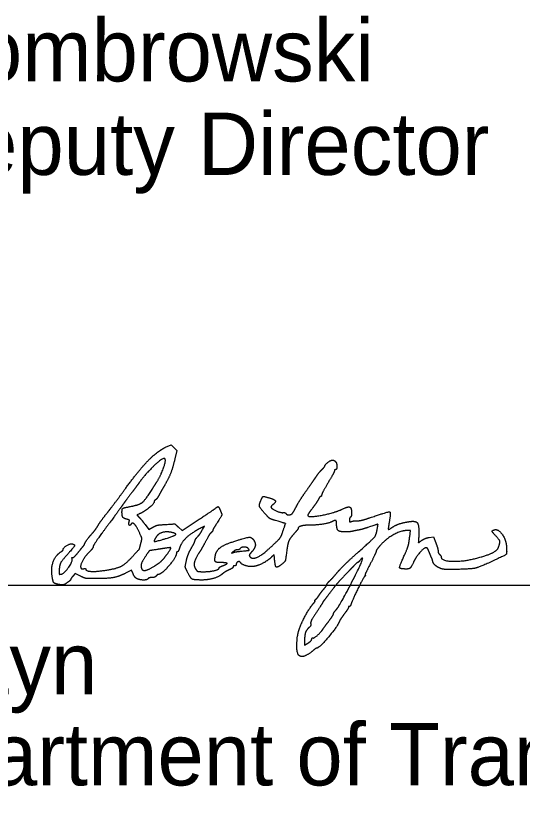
# Model space of a CAD drawing. Extents: x 0 to 42, y 0 to 22.
# Drawn here: x 25.7 to 26.838, y 7.063 to 8.834 of the extents above; entities that cross this region are included whole.
import ezdxf

# ---------------------------------------------------------------- set-up
doc = ezdxf.new("R2010")
doc.units = 0
for name, color, linetype in [('Default', 7, 'Continuous'), ('SH_Data', 7, 'Continuous'), ('SH_Text', 7, 'Continuous')]:
    doc.layers.add(name, color=color, linetype=linetype)

msp = doc.modelspace()

# ---------------------------------------------------------------- linework, layer by layer
at = {"layer": 'Default'}
for points in [[(26.0362, 7.8643), (26.0488, 7.8702), (26.0552, 7.8638), (26.0616, 7.8575), (26.0572, 7.8388)], [(25.9763, 7.7144), (25.9713, 7.7128), (25.9764, 7.7076)], [(25.9901, 7.691), (25.9987, 7.6794), (26.0075, 7.6847)], [(26.0653, 7.6847), (26.0734, 7.6771), (26.1096, 7.7012)], [(26.1191, 7.6794), (26.1236, 7.6873), (26.1181, 7.6844)], [(26.585, 7.6635), (26.5865, 7.6773), (26.5787, 7.6773)], [(26.6288, 7.6619), (26.6385, 7.6634), (26.6436, 7.6499)], [(26.2809, 7.6157), (26.2803, 7.6225), (26.2744, 7.6174)], [(25.8447, 7.5751), (25.8331, 7.5808), (25.8281, 7.575)], [(25.9633, 7.5801), (25.9599, 7.5881), (25.9461, 7.5813)], [(26.3487, 7.4296), (26.3487, 7.4202), (26.3562, 7.4245)]]:
    msp.add_lwpolyline(points, dxfattribs=at)
for points in [[(25.9467, 7.7725), (25.9763, 7.8131), (26.0181, 7.8559), (26.0362, 7.8643)], [(26.0348, 7.8385), (26.0311, 7.8422), (25.9926, 7.8065), (25.9772, 7.7852)], [(26.0165, 7.7865), (26.0259, 7.8014), (26.0379, 7.8354), (26.0348, 7.8385)], [(26.0572, 7.8388), (26.0522, 7.8176), (26.043, 7.794), (26.0336, 7.7781)], [(26.3943, 7.8224), (26.3943, 7.8252), (26.4075, 7.8355), (26.4112, 7.8356)], [(26.4112, 7.8356), (26.4132, 7.8356), (26.4162, 7.8344), (26.4178, 7.8328)], [(26.4178, 7.8328), (26.4213, 7.8293), (26.4216, 7.8141), (26.4183, 7.8141)], [(26.3739, 7.7971), (26.3778, 7.8029), (26.384, 7.8107), (26.3877, 7.8143)], [(26.3877, 7.8143), (26.3913, 7.8179), (26.3943, 7.8216), (26.3943, 7.8224)], [(26.4159, 7.8116), (26.4159, 7.8102), (26.4094, 7.7981), (26.4015, 7.7847)], [(26.4183, 7.8141), (26.4169, 7.8141), (26.4159, 7.813), (26.4159, 7.8116)], [(26.3523, 7.7661), (26.3602, 7.7773), (26.3699, 7.7913), (26.3739, 7.7971)], [(25.9772, 7.7852), (25.9736, 7.7802), (25.9642, 7.7675), (25.9563, 7.7571)], [(26.0059, 7.7698), (26.0092, 7.775), (26.014, 7.7825), (26.0165, 7.7865)], [(26.0336, 7.7781), (26.0301, 7.7721), (26.0249, 7.763), (26.022, 7.7577)], [(26.4015, 7.7847), (26.3935, 7.7713), (26.3871, 7.7589), (26.3871, 7.7572)], [(25.9065, 7.719), (25.9154, 7.7303), (25.9335, 7.7544), (25.9467, 7.7725)], [(25.9562, 7.7312), (25.9768, 7.7349), (25.9908, 7.7458), (26.0059, 7.7698)], [(26.022, 7.7577), (26.0192, 7.7524), (26.0154, 7.7472), (26.0135, 7.7462)], [(26.3309, 7.7325), (26.3347, 7.7397), (26.3443, 7.7549), (26.3523, 7.7661)], [(25.9563, 7.7571), (25.9483, 7.7466), (25.9402, 7.7356), (25.9383, 7.7326)], [(26.0103, 7.7408), (26.0103, 7.737), (25.9845, 7.717), (25.9763, 7.7144)], [(26.0135, 7.7462), (26.0117, 7.7451), (26.0103, 7.7427), (26.0103, 7.7408)], [(26.26, 7.7149), (26.2485, 7.728), (26.2462, 7.7348), (26.2502, 7.7444)], [(26.2502, 7.7444), (26.254, 7.7534), (26.2571, 7.7544), (26.2698, 7.7506)], [(26.2698, 7.7506), (26.2818, 7.7471), (26.2846, 7.7409), (26.277, 7.7351)], [(26.3798, 7.7475), (26.378, 7.7439), (26.3719, 7.7348), (26.3662, 7.7273)], [(26.3851, 7.7541), (26.384, 7.7541), (26.3816, 7.7511), (26.3798, 7.7475)], [(26.3871, 7.7572), (26.3871, 7.7555), (26.3862, 7.7541), (26.3851, 7.7541)], [(25.9383, 7.7326), (25.9363, 7.7297), (25.9209, 7.7087), (25.9041, 7.6861)], [(25.9383, 7.719), (25.9383, 7.7259), (25.9424, 7.7287), (25.9562, 7.7312)], [(26.1096, 7.7012), (26.1296, 7.7144), (26.1472, 7.7263), (26.1488, 7.7277)], [(26.1488, 7.7277), (26.1533, 7.7314), (26.1557, 7.7306), (26.1587, 7.724)], [(26.1587, 7.724), (26.1631, 7.7143), (26.1621, 7.7102), (26.1519, 7.6944)], [(26.277, 7.7351), (26.2742, 7.733), (26.2728, 7.7302), (26.2737, 7.7288)], [(26.2737, 7.7288), (26.2764, 7.725), (26.2963, 7.7168), (26.3009, 7.7176)], [(26.3216, 7.7163), (26.3229, 7.7179), (26.3271, 7.7252), (26.3309, 7.7325)], [(26.3662, 7.7273), (26.3605, 7.7198), (26.3559, 7.7126), (26.3559, 7.7112)], [(26.3559, 7.7112), (26.3559, 7.7059), (26.4155, 7.7169), (26.4334, 7.7254)], [(26.4334, 7.7254), (26.4464, 7.7316), (26.4543, 7.7285), (26.4543, 7.7171)], [(25.885, 7.6896), (25.8879, 7.6945), (25.8976, 7.7077), (25.9065, 7.719)], [(25.9493, 7.7027), (25.9421, 7.7044), (25.9383, 7.7102), (25.9383, 7.719)], [(25.9764, 7.7076), (25.9793, 7.7048), (25.9854, 7.6973), (25.9901, 7.691)], [(26.2835, 7.6998), (26.2727, 7.7029), (26.2678, 7.7061), (26.26, 7.7149)], [(26.3009, 7.7176), (26.3032, 7.718), (26.3057, 7.7172), (26.3066, 7.7158)], [(26.3066, 7.7158), (26.3087, 7.7123), (26.3188, 7.7126), (26.3216, 7.7163)], [(26.4519, 7.7073), (26.4505, 7.7065), (26.4495, 7.7036), (26.4495, 7.701)], [(26.4543, 7.7171), (26.4543, 7.7125), (26.4532, 7.7081), (26.4519, 7.7073)], [(26.4678, 7.6993), (26.472, 7.6992), (26.4849, 7.7023), (26.4966, 7.7064)], [(26.4966, 7.7064), (26.537, 7.7203), (26.5429, 7.7186), (26.5388, 7.6947)], [(25.8687, 7.6678), (25.8752, 7.6751), (25.8795, 7.6808), (25.885, 7.6896)], [(25.9543, 7.6964), (25.9553, 7.6999), (25.954, 7.7015), (25.9493, 7.7027)], [(25.9586, 7.6916), (25.9562, 7.6877), (25.953, 7.6913), (25.9543, 7.6964)], [(25.9774, 7.673), (25.9713, 7.6867), (25.9615, 7.6963), (25.9586, 7.6916)], [(26.0075, 7.6847), (26.014, 7.6885), (26.0216, 7.6902), (26.0367, 7.6911)], [(26.0367, 7.6911), (26.057, 7.6923), (26.0572, 7.6922), (26.0653, 7.6847)], [(26.1519, 7.6944), (26.1466, 7.6862), (26.1423, 7.6786), (26.1423, 7.6775)], [(26.3002, 7.676), (26.3059, 7.6929), (26.3055, 7.6934), (26.2835, 7.6998)], [(26.3585, 7.6893), (26.347, 7.6893), (26.3343, 7.6855), (26.3343, 7.6821)], [(26.4092, 7.6967), (26.4036, 7.6937), (26.3735, 7.6893), (26.3585, 7.6893)], [(26.4207, 7.6919), (26.4207, 7.6993), (26.417, 7.7008), (26.4092, 7.6967)], [(26.44, 7.6743), (26.4276, 7.6743), (26.4207, 7.6806), (26.4207, 7.6919)], [(26.4495, 7.701), (26.4495, 7.6971), (26.4505, 7.6965), (26.4549, 7.6979)], [(26.4549, 7.6979), (26.4578, 7.6988), (26.4637, 7.6995), (26.4678, 7.6993)], [(26.5119, 7.6797), (26.514, 7.6912), (26.5122, 7.6916), (26.4912, 7.6844)], [(26.5388, 7.6947), (26.5374, 7.6871), (26.5367, 7.6805), (26.5372, 7.68)], [(26.5447, 7.6839), (26.552, 7.689), (26.5702, 7.6953), (26.5839, 7.6974)], [(26.5839, 7.6974), (26.5985, 7.6997), (26.6062, 7.6893), (26.6054, 7.6681)], [(25.9041, 7.6861), (25.8873, 7.6634), (25.8735, 7.6433), (25.8735, 7.6413)], [(25.9807, 7.6485), (25.9833, 7.6583), (25.983, 7.6605), (25.9774, 7.673)], [(26.0485, 7.6734), (26.0376, 7.6755), (26.0202, 7.6705), (26.0159, 7.6639)], [(26.0379, 7.6598), (26.0571, 7.6657), (26.0611, 7.6708), (26.0485, 7.6734)], [(26.1181, 7.6844), (26.0947, 7.6719), (26.0719, 7.6512), (26.0678, 7.6387)], [(26.1064, 7.6613), (26.1118, 7.6673), (26.1143, 7.6708), (26.1191, 7.6794)], [(26.1387, 7.6725), (26.1368, 7.6709), (26.1337, 7.6667), (26.1318, 7.6632)], [(26.1423, 7.6775), (26.1423, 7.6764), (26.1407, 7.6741), (26.1387, 7.6725)], [(26.2819, 7.6487), (26.2924, 7.6588), (26.2965, 7.6649), (26.3002, 7.676)], [(26.3249, 7.6701), (26.3164, 7.6606), (26.3107, 7.648), (26.3091, 7.6353)], [(26.3343, 7.6821), (26.3343, 7.6812), (26.3301, 7.6758), (26.3249, 7.6701)], [(26.4567, 7.6757), (26.4534, 7.6749), (26.4459, 7.6743), (26.44, 7.6743)], [(26.4699, 7.6783), (26.4659, 7.6777), (26.46, 7.6765), (26.4567, 7.6757)], [(26.467, 7.6268), (26.5025, 7.6583), (26.5094, 7.6665), (26.5119, 7.6797)], [(26.4912, 7.6844), (26.4834, 7.6817), (26.4738, 7.679), (26.4699, 7.6783)], [(26.5787, 7.6773), (26.566, 7.6773), (26.5322, 7.6589), (26.52, 7.6453)], [(26.5372, 7.68), (26.5376, 7.6795), (26.541, 7.6813), (26.5447, 7.6839)], [(26.7755, 7.6687), (26.7702, 7.6744), (26.7699, 7.677), (26.7745, 7.6788)], [(26.7745, 7.6788), (26.7831, 7.6821), (26.8016, 7.6571), (26.8026, 7.6409)], [(25.8543, 7.6473), (25.8543, 7.6489), (25.8634, 7.6619), (25.8687, 7.6678)], [(26.0159, 7.6639), (26.0089, 7.6531), (26.0134, 7.6523), (26.0379, 7.6598)], [(26.0939, 7.6372), (26.0983, 7.6448), (26.1021, 7.6525), (26.1024, 7.6542)], [(26.1024, 7.6542), (26.1026, 7.656), (26.1044, 7.6591), (26.1064, 7.6613)], [(26.1318, 7.6632), (26.1237, 7.6478), (26.1159, 7.6341), (26.1098, 7.6243)], [(26.148, 7.6205), (26.1501, 7.6317), (26.1663, 7.6451), (26.1856, 7.6515)], [(26.1856, 7.6515), (26.2175, 7.6621), (26.2309, 7.6625), (26.236, 7.6531)], [(26.236, 7.6531), (26.2392, 7.647), (26.2358, 7.6357), (26.2284, 7.6278)], [(26.5703, 7.6156), (26.5794, 7.6355), (26.5834, 7.6487), (26.585, 7.6635)], [(26.6054, 7.6681), (26.6047, 7.6497), (26.6046, 7.6499), (26.6123, 7.6554)], [(26.6123, 7.6554), (26.6161, 7.6581), (26.6235, 7.661), (26.6288, 7.6619)], [(26.7846, 7.6396), (26.7885, 7.6514), (26.787, 7.6563), (26.7755, 7.6687)], [(25.8016, 7.6299), (25.8042, 7.6315), (25.8063, 7.6339), (25.8063, 7.6353)], [(25.8063, 7.6353), (25.8063, 7.639), (25.8231, 7.649), (25.8269, 7.6475)], [(25.8269, 7.6475), (25.8328, 7.6452), (25.8306, 7.6404), (25.8162, 7.6244)], [(25.8397, 7.6281), (25.8451, 7.6347), (25.8505, 7.6414), (25.8519, 7.643)], [(25.8519, 7.643), (25.8532, 7.6446), (25.8543, 7.6465), (25.8543, 7.6473)], [(25.8735, 7.6413), (25.8734, 7.6393), (25.8701, 7.6345), (25.8661, 7.6306)], [(25.9611, 7.618), (25.9771, 7.6356), (25.9775, 7.6361), (25.9807, 7.6485)], [(26.0187, 7.635), (26.0009, 7.6325), (25.9988, 7.6313), (25.9916, 7.6201)], [(26.0361, 7.6377), (26.0305, 7.6368), (26.0226, 7.6356), (26.0187, 7.635)], [(26.041, 7.6261), (26.0489, 7.6374), (26.0479, 7.6396), (26.0361, 7.6377)], [(26.0678, 7.6387), (26.0661, 7.6335), (26.0638, 7.6293), (26.0627, 7.6293)], [(26.083, 7.6093), (26.0846, 7.617), (26.0895, 7.6295), (26.0939, 7.6372)], [(26.1978, 7.6341), (26.1955, 7.6341), (26.1915, 7.6324), (26.1889, 7.6303)], [(26.2033, 7.6362), (26.2026, 7.635), (26.2001, 7.6341), (26.1978, 7.6341)], [(26.2218, 7.6373), (26.219, 7.6407), (26.2056, 7.6399), (26.2033, 7.6362)], [(26.2059, 7.631), (26.2226, 7.6325), (26.225, 7.6334), (26.2218, 7.6373)], [(26.225, 7.6199), (26.2303, 7.6112), (26.257, 7.6247), (26.2819, 7.6487)], [(26.3091, 7.6353), (26.3063, 7.6128), (26.3045, 7.6073), (26.2989, 7.6028)], [(26.52, 7.6453), (26.5142, 7.6388), (26.5095, 7.6323), (26.5095, 7.6307)], [(26.6219, 7.6389), (26.6176, 7.6389), (26.5993, 7.6184), (26.5946, 7.6082)], [(26.6275, 7.6323), (26.626, 7.6359), (26.6235, 7.6389), (26.6219, 7.6389)], [(26.6436, 7.6499), (26.6464, 7.6424), (26.6487, 7.6343), (26.6487, 7.6318)], [(26.7357, 7.6153), (26.7594, 7.6215), (26.7823, 7.6329), (26.7846, 7.6396)], [(26.8026, 7.6409), (26.8035, 7.6255), (26.8009, 7.6224), (26.7774, 7.6114)], [(25.7814, 7.5736), (25.7784, 7.5922), (25.7892, 7.6222), (25.8016, 7.6299)], [(25.8162, 7.6244), (25.8026, 7.6093), (25.7976, 7.5991), (25.797, 7.5853)], [(25.8263, 7.6139), (25.8255, 7.6159), (25.826, 7.6172), (25.8275, 7.6168)], [(25.8275, 7.6168), (25.8289, 7.6164), (25.8344, 7.6215), (25.8397, 7.6281)], [(25.8661, 7.6306), (25.8562, 7.6209), (25.8439, 7.5988), (25.8457, 7.5941)], [(25.9046, 7.5886), (25.9273, 7.5923), (25.9469, 7.6025), (25.9611, 7.618)], [(25.9916, 7.6201), (25.9834, 7.6075), (25.9802, 7.5976), (25.9824, 7.5918)], [(26.0112, 7.5974), (26.0223, 7.6043), (26.0333, 7.6149), (26.041, 7.6261)], [(26.0606, 7.6263), (26.0605, 7.6177), (26.0274, 7.5789), (26.0203, 7.5789)], [(26.0627, 7.6293), (26.0616, 7.6293), (26.0606, 7.6279), (26.0606, 7.6263)], [(26.1098, 7.6243), (26.1018, 7.6117), (26.0996, 7.5965), (26.1047, 7.5897)], [(26.1616, 7.6053), (26.1501, 7.6053), (26.146, 7.6098), (26.148, 7.6205)], [(26.1889, 7.6303), (26.1843, 7.6265), (26.1843, 7.6265), (26.1891, 7.6282)], [(26.1891, 7.6282), (26.1917, 7.6291), (26.1993, 7.6304), (26.2059, 7.631)], [(26.2284, 7.6278), (26.2256, 7.6248), (26.2241, 7.6213), (26.225, 7.6199)], [(26.2744, 7.6174), (26.265, 7.6092), (26.245, 7.5986), (26.2359, 7.5969)], [(26.423, 7.584), (26.4302, 7.5924), (26.45, 7.6117), (26.467, 7.6268)], [(26.5095, 7.6307), (26.5095, 7.6291), (26.5035, 7.6163), (26.4962, 7.6022)], [(26.6334, 7.6181), (26.6316, 7.6223), (26.6289, 7.6287), (26.6275, 7.6323)], [(26.6367, 7.6085), (26.6367, 7.6096), (26.6352, 7.614), (26.6334, 7.6181)], [(26.6487, 7.6318), (26.6487, 7.6293), (26.6503, 7.6256), (26.6523, 7.6236)], [(26.6523, 7.6236), (26.6542, 7.6216), (26.6559, 7.619), (26.6559, 7.6176)], [(26.6559, 7.6176), (26.6559, 7.6091), (26.7065, 7.6076), (26.7357, 7.6153)], [(25.8018, 7.5793), (25.8081, 7.5803), (25.8282, 7.6087), (25.8263, 7.6139)], [(26.085, 7.5853), (26.0805, 7.5944), (26.0804, 7.5966), (26.083, 7.6093)], [(26.1567, 7.5935), (26.1567, 7.5945), (26.1604, 7.5967), (26.1649, 7.5984)], [(26.1649, 7.5984), (26.1752, 7.6021), (26.1737, 7.6053), (26.1616, 7.6053)], [(26.1951, 7.6014), (26.1951, 7.5996), (26.1934, 7.5981), (26.1915, 7.5981)], [(26.2046, 7.6054), (26.2025, 7.6087), (26.1951, 7.6056), (26.1951, 7.6014)], [(26.2359, 7.5969), (26.2273, 7.5954), (26.2075, 7.6008), (26.2046, 7.6054)], [(26.2989, 7.6028), (26.2871, 7.5936), (26.2827, 7.5968), (26.2809, 7.6157)], [(26.4204, 7.5002), (26.428, 7.5089), (26.4813, 7.6127), (26.4792, 7.6148)], [(26.4677, 7.6053), (26.4669, 7.6053), (26.463, 7.6018), (26.4589, 7.5975)], [(26.4735, 7.6107), (26.4711, 7.6077), (26.4685, 7.6053), (26.4677, 7.6053)], [(26.4792, 7.6148), (26.4784, 7.6155), (26.4759, 7.6137), (26.4735, 7.6107)], [(26.4962, 7.6022), (26.489, 7.588), (26.4838, 7.5765), (26.4848, 7.5764)], [(26.5777, 7.5909), (26.5632, 7.5909), (26.5615, 7.5963), (26.5703, 7.6156)], [(26.5946, 7.6082), (26.5888, 7.5958), (26.584, 7.5909), (26.5777, 7.5909)], [(26.6524, 7.593), (26.6453, 7.5963), (26.6369, 7.6047), (26.6367, 7.6085)], [(26.7774, 7.6114), (26.7426, 7.5951), (26.7216, 7.5904), (26.6823, 7.5899)], [(25.797, 7.5853), (25.7967, 7.5797), (25.7976, 7.5787), (25.8018, 7.5793)], [(25.8457, 7.5941), (25.8466, 7.5917), (25.8489, 7.5908), (25.8519, 7.5916)], [(25.8519, 7.5916), (25.8545, 7.5923), (25.8567, 7.5919), (25.8567, 7.5908)], [(25.8567, 7.5908), (25.8567, 7.5862), (25.8823, 7.585), (25.9046, 7.5886)], [(25.9461, 7.5813), (25.9305, 7.5736), (25.9053, 7.5693), (25.8754, 7.5693)], [(25.9824, 7.5918), (25.9844, 7.5866), (25.998, 7.5892), (26.0112, 7.5974)], [(26.1167, 7.5662), (26.0992, 7.5663), (26.0922, 7.5705), (26.085, 7.5853)], [(26.1047, 7.5897), (26.1075, 7.5859), (26.1111, 7.5849), (26.1223, 7.5849)], [(26.1223, 7.5849), (26.1362, 7.5849), (26.1567, 7.59), (26.1567, 7.5935)], [(26.1825, 7.5907), (26.1751, 7.5874), (26.1675, 7.5829), (26.1633, 7.5794)], [(26.1879, 7.5956), (26.1879, 7.5943), (26.1854, 7.5921), (26.1825, 7.5907)], [(26.1915, 7.5981), (26.1895, 7.5981), (26.1879, 7.597), (26.1879, 7.5956)], [(26.4045, 7.5636), (26.4075, 7.5664), (26.4158, 7.5756), (26.423, 7.584)], [(26.4589, 7.5975), (26.4548, 7.5932), (26.4443, 7.5821), (26.4355, 7.5728)], [(26.6823, 7.5899), (26.6673, 7.5897), (26.657, 7.5908), (26.6524, 7.593)], [(25.798, 7.5559), (25.7871, 7.5579), (25.7833, 7.562), (25.7814, 7.5736)], [(25.823, 7.5675), (25.823, 7.5665), (25.8193, 7.5631), (25.8147, 7.56)], [(25.8281, 7.575), (25.8253, 7.5719), (25.8231, 7.5684), (25.823, 7.5675)], [(25.8754, 7.5693), (25.8599, 7.5693), (25.854, 7.5704), (25.8447, 7.5751)], [(25.9715, 7.5695), (25.9688, 7.5709), (25.9651, 7.5757), (25.9633, 7.5801)], [(25.9971, 7.5693), (25.9951, 7.5661), (25.9776, 7.5662), (25.9715, 7.5695)], [(26.0053, 7.5717), (26.0016, 7.5717), (25.9979, 7.5706), (25.9971, 7.5693)], [(26.0151, 7.5753), (26.0134, 7.5733), (26.009, 7.5717), (26.0053, 7.5717)], [(26.0203, 7.5789), (26.019, 7.5789), (26.0167, 7.5773), (26.0151, 7.5753)], [(26.1633, 7.5794), (26.1556, 7.573), (26.1312, 7.5661), (26.1167, 7.5662)], [(26.3991, 7.5564), (26.3991, 7.5575), (26.4016, 7.5608), (26.4045, 7.5636)], [(26.4355, 7.5728), (26.4267, 7.5636), (26.4168, 7.5523), (26.4135, 7.5479)], [(26.4841, 7.5746), (26.4814, 7.5728), (26.4562, 7.5218), (26.4532, 7.5123)], [(26.4848, 7.5764), (26.4858, 7.5764), (26.4855, 7.5756), (26.4841, 7.5746)], [(25.8147, 7.56), (25.8082, 7.5556), (25.8045, 7.5547), (25.798, 7.5559)], [(26.3823, 7.5333), (26.3842, 7.5363), (26.3888, 7.5423), (26.3925, 7.5466)], [(26.4135, 7.5479), (26.4054, 7.5369), (26.3949, 7.5231), (26.3919, 7.5196)], [(26.3925, 7.5466), (26.3961, 7.5508), (26.3991, 7.5553), (26.3991, 7.5564)], [(26.3745, 7.5233), (26.3768, 7.5257), (26.3803, 7.5302), (26.3823, 7.5333)], [(26.3385, 7.4609), (26.3444, 7.4757), (26.3615, 7.5056), (26.3686, 7.5135)], [(26.3686, 7.5135), (26.3713, 7.5165), (26.3728, 7.5189), (26.3719, 7.5189)], [(26.3719, 7.5189), (26.371, 7.5189), (26.3722, 7.5209), (26.3745, 7.5233)], [(26.3895, 7.5157), (26.3895, 7.5152), (26.3831, 7.5052), (26.3754, 7.4936)], [(26.3919, 7.5196), (26.3906, 7.518), (26.3895, 7.5162), (26.3895, 7.5157)], [(26.4532, 7.5123), (26.4523, 7.5093), (26.4505, 7.5069), (26.4493, 7.5069)], [(26.3754, 7.4936), (26.3667, 7.4806), (26.3618, 7.4708), (26.3625, 7.4681)], [(26.4135, 7.4899), (26.4135, 7.4912), (26.4166, 7.4959), (26.4204, 7.5002)], [(26.4471, 7.5044), (26.4471, 7.503), (26.4428, 7.4962), (26.4376, 7.4893)], [(26.4493, 7.5069), (26.4481, 7.5069), (26.4471, 7.5058), (26.4471, 7.5044)], [(26.4033, 7.4741), (26.4089, 7.4814), (26.4135, 7.4886), (26.4135, 7.4899)], [(26.4376, 7.4893), (26.4324, 7.4824), (26.4272, 7.4745), (26.4262, 7.4716)], [(26.3367, 7.3964), (26.3307, 7.4002), (26.332, 7.4445), (26.3385, 7.4609)], [(26.3588, 7.4595), (26.3528, 7.4543), (26.3487, 7.4419), (26.3487, 7.4296)], [(26.3625, 7.4681), (26.3631, 7.4656), (26.3616, 7.4619), (26.3588, 7.4595)], [(26.3679, 7.4361), (26.3698, 7.4349), (26.3864, 7.45), (26.3907, 7.4568)], [(26.4262, 7.4716), (26.4225, 7.4618), (26.3814, 7.4133), (26.3767, 7.4133)], [(26.3907, 7.4568), (26.392, 7.4589), (26.3977, 7.4667), (26.4033, 7.4741)], [(26.3562, 7.4245), (26.3603, 7.4269), (26.3642, 7.4308), (26.3649, 7.4331)], [(26.3649, 7.4331), (26.3655, 7.4354), (26.3668, 7.4367), (26.3679, 7.4361)], [(26.3692, 7.4087), (26.363, 7.403), (26.3471, 7.3941), (26.3432, 7.3941)], [(26.3767, 7.4133), (26.3753, 7.4133), (26.3719, 7.4112), (26.3692, 7.4087)], [(26.3432, 7.3941), (26.3416, 7.3941), (26.3386, 7.3952), (26.3367, 7.3964)]]:
    msp.add_open_spline(points, degree=2, dxfattribs=at)
at = {"layer": 'SH_Data'}
msp.add_line((24.5408, 7.5548), (28.0408, 7.5548), dxfattribs=at)

# ---------------------------------------------------------------- texts
at = {"layer": 'SH_Text'}
for s, p in [('Michael G. Dombrowski', (24.5279, 8.6862)), ('District       Deputy Director', (24.5279, 8.4762)), ('Pamela Boratyn', (24.551, 7.3091)), ('Director, Department of Transportation', (24.5408, 7.1048))]:
    msp.add_text(s, height=0.14, dxfattribs=at).set_placement(p)

doc.saveas('drawing.dxf')
